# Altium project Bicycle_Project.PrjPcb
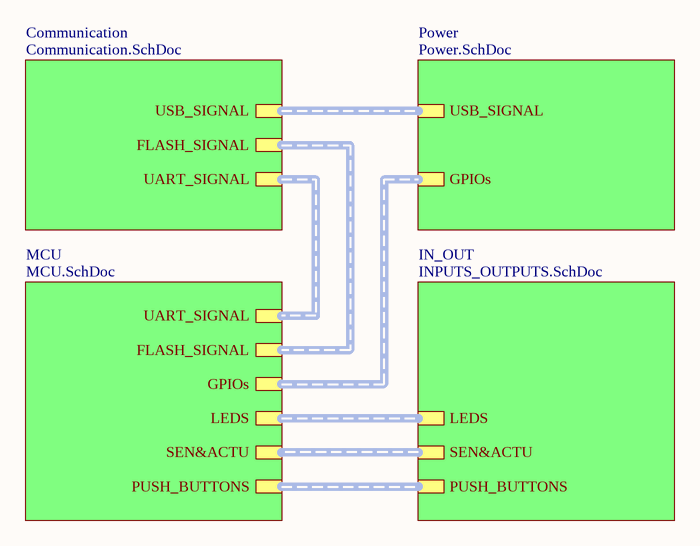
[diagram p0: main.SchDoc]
5 sheets, 108 parts. Net scope: hierarchical (ports join the sheet entries above them; power ports are global).
Board file: Bicycle_Project.PcbDoc
Sheets:
  main.SchDoc
    Communication = Communication.SchDoc
    MCU = MCU.SchDoc
    Power = Power.SchDoc
    IN_OUT = INPUTS_OUTPUTS.SchDoc

## Sheet main.SchDoc: BICYCLE_PROJECT
size A4; SheetNumber: 1; SheetTotal: 5

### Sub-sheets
Communication = Communication.SchDoc: USB_SIGNAL (harness USB_SIGNAL), UART_SIGNAL (harness UART_SIGNAL), FLASH_SIGNAL (harness FLASH_SIGNAL)
IN_OUT = INPUTS_OUTPUTS.SchDoc: LEDS (harness LEDS), PUSH_BUTTONS (harness PUSH_BUTTONS), SEN&ACTU (harness SENSORS&ACTUATORS)
MCU = MCU.SchDoc: UART_SIGNAL (harness UART_SIGNAL), LEDS (harness LEDS), PUSH_BUTTONS (harness PUSH_BUTTONS), FLASH_SIGNAL (harness FLASH_SIGNAL), SEN&ACTU (harness SENSORS&ACTUATORS), GPIOs (harness GPIOs)
Power = Power.SchDoc: USB_SIGNAL (harness USB_SIGNAL), GPIOs (harness GPIOs)

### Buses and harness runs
harness sheet Communication/FLASH_SIGNAL = sheet MCU/FLASH_SIGNAL
harness sheet Communication/UART_SIGNAL = sheet MCU/UART_SIGNAL
harness sheet Communication/USB_SIGNAL = sheet Power/USB_SIGNAL
harness sheet IN_OUT/LEDS = sheet MCU/LEDS
harness sheet IN_OUT/PUSH_BUTTONS = sheet MCU/PUSH_BUTTONS
harness sheet IN_OUT/SEN&ACTU = sheet MCU/SEN&ACTU
harness sheet MCU/GPIOs = sheet Power/GPIOs

## Sheet Communication.SchDoc
size A4; SheetNumber: 4; SheetTotal: 5
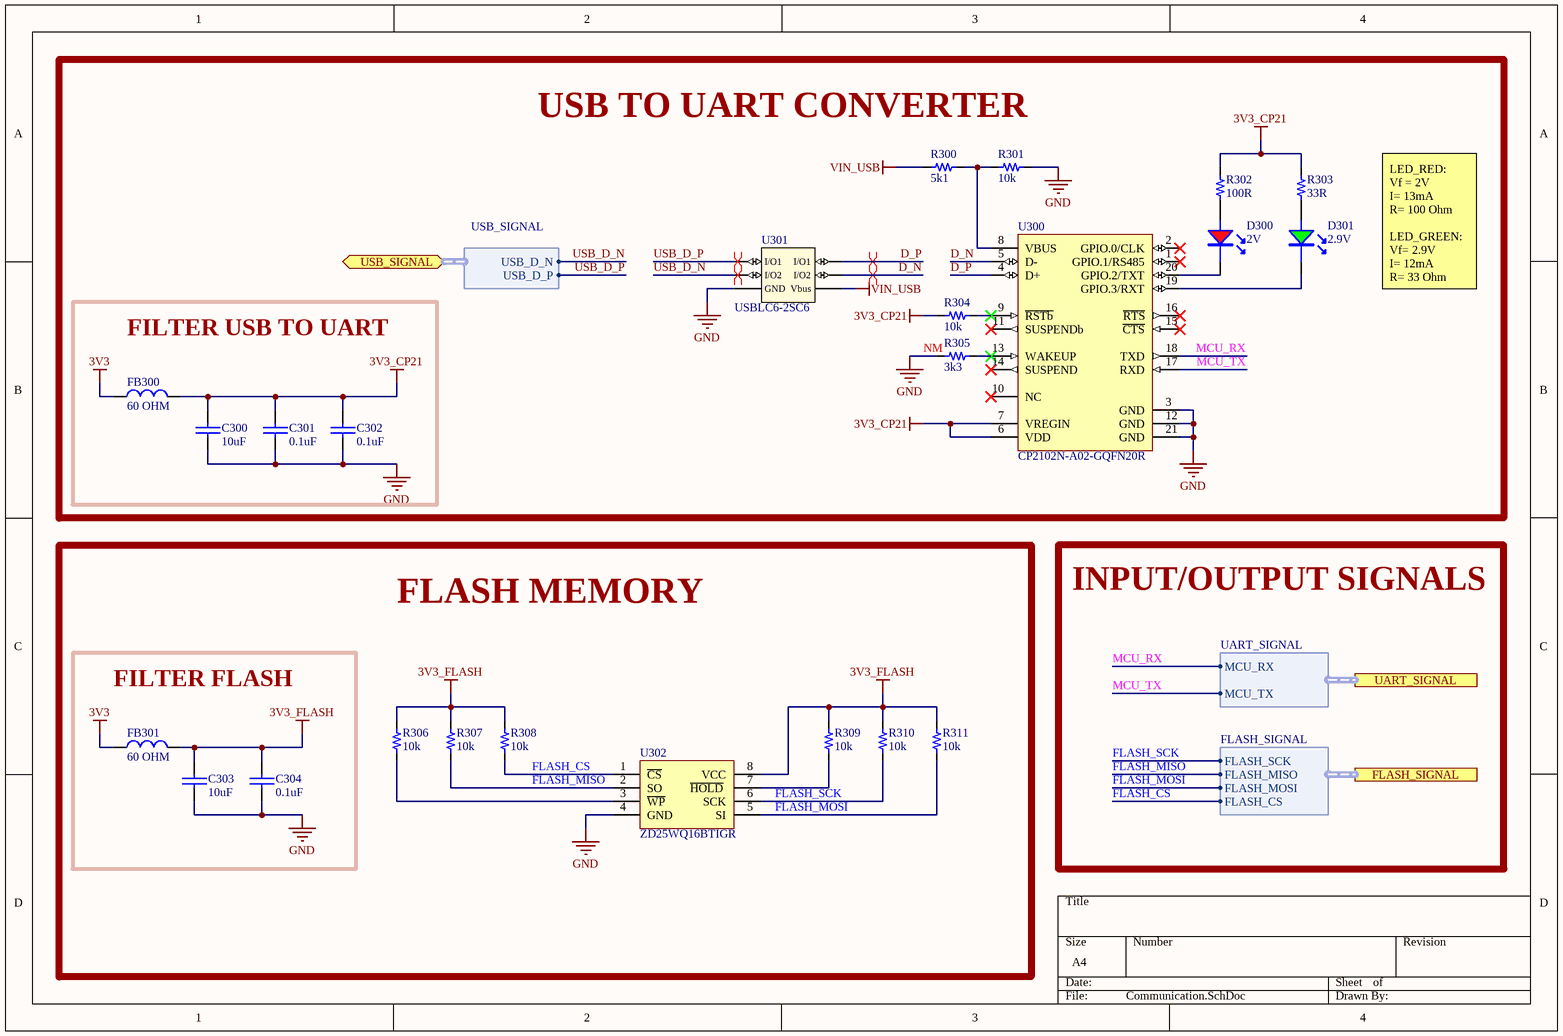
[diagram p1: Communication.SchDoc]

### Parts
C300  value 10uF  [0603_cap]  (hidden comment: 10uF 10V)
C301  value 0.1uF  [0603_cap]  (hidden comment: 0.1uF 50V)
C302  value 0.1uF  [0603_cap]  (hidden comment: 0.1uF 50V)
C303  value 10uF  [0603_cap]  (hidden comment: 10uF 10V)
C304  value 0.1uF  [0603_cap]  (hidden comment: 0.1uF 50V)
D300  2V  [0805_LED]
D301  2.9V  [0805_LED]
FB300  value 60 OHM  [0603_fb]  (hidden comment: 60OHM 2A)
FB301  value 60 OHM  [0603_fb]  (hidden comment: 60OHM 2A)
R300  value 5k1  [0603_res]  (hidden comment: 5k1 1/10W)
R301  value 10k  [0603_res]  (hidden comment: 10k 1/10W)
R302  value 100R  [0603_res]  (hidden comment: 100R 1/10W)
R303  value 33R  [0603_res]  (hidden comment: 33R 1/10W)
R304  value 10k  [0603_res]  (hidden comment: 10k 1/10W)
R305  value 3k3  Usage: NM  [0603_res]  (hidden comment: 3k3 1/10W)
R306  value 10k  [0603_res]  (hidden comment: 10k 1/10W)
R307  value 10k  [0603_res]  (hidden comment: 10k 1/10W)
R308  value 10k  [0603_res]  (hidden comment: 10k 1/10W)
R309  value 10k  [0603_res]  (hidden comment: 10k 1/10W)
R310  value 10k  [0603_res]  (hidden comment: 10k 1/10W)
R311  value 10k  [0603_res]  (hidden comment: 10k 1/10W)
U300  CP2102N-A02-GQFN20R  [WFQFN_20_EP_3X3MM]
U301  USBLC6-2SC6  [SOT_23_6]
U302  ZD25WQ16BTIGR  [SOIC_8_3.9mm]

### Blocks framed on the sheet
USB TO UART CONVERTER: D300 D301 R300-R305 U300 U301
FILTER USB TO UART: C300-C302 FB300
FLASH MEMORY: R306-R311 U302
FILTER FLASH: C303 C304 FB301

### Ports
FLASH_SIGNAL (harness FLASH_SIGNAL, see main[3B], MCU[4B]), UART_SIGNAL (harness UART_SIGNAL, see main[3B], MCU[4D]), USB_SIGNAL (bidir, harness USB_SIGNAL, see main[3B], Power[2A])

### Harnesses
USB_SIGNAL: USB_D_N, USB_D_P
UART_SIGNAL: MCU_TX, MCU_RX
FLASH_SIGNAL: FLASH_SCK, FLASH_MISO, FLASH_MOSI, FLASH_CS

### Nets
3V3: FB300.1 FB301.2
3V3_CP21: C300.1 C301.1 C302.1 FB300.2 R302.2 R303.2 R304.1 U300.6(VDD) U300.7(VREGIN)
3V3_FLASH: C303.1 C304.1 FB301.1 R306.2 R307.2 R308.1 R309.2 R310.2 R311.2 U302.8(VCC)
GND: C300.2 C301.2 C302.2 C303.2 C304.2 R301.2 R305.1 U300.3(GND) U300.12(GND) U300.21(GND) U301.2(GND) U302.4(GND)
VIN_USB: R300.1 U301.5(Vbus)
D_N: U300.5(D-) U301.4(I/O2)
D_P: U300.4(D+) U301.6(I/O1)
FLASH_CS: R308.2 U302.1(~{CS}) ; port FLASH_SIGNAL.FLASH_CS
FLASH_MISO: R307.1 U302.2(SO) ; port FLASH_SIGNAL.FLASH_MISO
FLASH_MOSI: R311.1 U302.5(SI) ; port FLASH_SIGNAL.FLASH_MOSI
FLASH_SCK: R310.1 U302.6(SCK) ; port FLASH_SIGNAL.FLASH_SCK
MCU_RX: U300.18(TXD) ; port UART_SIGNAL.MCU_RX
MCU_TX: U300.17(RXD) ; port UART_SIGNAL.MCU_TX
USB_D_N: U301.3(I/O2) ; port USB_SIGNAL.USB_D_N
USB_D_P: U301.1(I/O1) ; port USB_SIGNAL.USB_D_P
NetD300_1: D300.1(A) R302.1
NetD300_2: D300.2 U300.20(GPIO.2/TXT)
NetD301_1: D301.1(A) R303.1
NetD301_2: D301.2 U300.19(GPIO.3/RXT)
NetR300_2: R300.2 R301.1 U300.8(VBUS)
NetR304_2: R304.2 U300.9(~{RSTb})
NetR305_2: R305.2 U300.13(WAKEUP)
NetR306_1: R306.1 U302.3(~{WP})
NetR309_1: R309.1 U302.7(~{HOLD})

Not connected (* = marked no-connect by the designer): U300 1(GPIO.1/RS485)* 2(GPIO.0/CLK)* 10(NC)* 11(SUSPENDb)* 14(SUSPEND)* 15(~{CTS})* 16(~{RTS})*

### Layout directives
differential pair: D_N, D_P, USB_D_N, USB_D_P

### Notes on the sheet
- LED_RED:
  Vf = 2V
  I= 13mA
  R= 100 Ohm
  LED_GREEN:
  Vf= 2.9V
  I= 12mA
  R= 33 Ohm
- INPUT/OUTPUT SIGNALS

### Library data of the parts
C300 C303 = Cap_10uF_0603_10V: 10V 10uF X5R ±10% 0603 Multilayer Ceramic Capacitors MLCC - SMD/SMT ROHS; Manufacturer: CCTC; Manufacturer Part Number: TCC0603X5R106K100CT
C301 C302 C304 = Cap_0.1uF_0603_50V: 50V 100nF Y5V -20%~+80% 0603 Multilayer Ceramic Capacitors MLCC - SMD/SMT ROHS; Manufacturer: Walsin Tech Corp; Manufacturer Part Number: 0603F104Z500CT
D300 = LED_0805_RED: LED RED CLEAR 0805 SMD; Manufacturer: XINGLIGHT; Manufacturer Part Number: XL-2012SURC
D301 = LED_0805_Green: LED GREEN CLEAR 0805 SMD; Manufacturer: XINGLIGHT; Manufacturer Part Number: XL-2012UGC
FB300 FB301 = FB_60_0603_2A: 2A 1 100mΩ 60Ω@100MHz ±25% 0603 Ferrite Beads ROHS; Manufacturer: TAI-TECH; Manufacturer Part Number: HCB1608KF-600T20
R300 = Res_5k1_0603_1/10W: RES SMD 5k1 OHM 5% 1/10W 0603; Manufacturer: FOJAN; Manufacturer Part Number: FRC0603J512 TS
R301 R304 R306-R311 = Res_10k_0603_1/10W: RES SMD 10k OHM 5% 1/10W 0603; Manufacturer: FOJAN; Manufacturer Part Number: FRC0603J103TS
R302 = Res_100R_0603_1/10W: RES SMD 100R OHM 5% 1/10W 0603; Manufacturer: FOJAN; Manufacturer Part Number: FRC0603J101 TS
R303 = Res_33R_0603_1/10W: RES SMD 33R OHM 5% 1/10W 0603; Manufacturer: FOJAN; Manufacturer Part Number: FRC0603J330 TS
R305 = Res_3k3_0603_1/10W: RES SMD 3k3 OHM 5% 1/10W 0603; Manufacturer: FOJAN; Manufacturer Part Number: FRC0603J332 TS
U300 = IC_SGL_USB2UART-BRIDGE_20QFN: IC USB TO UART BRIDGE QFN20; Manufacturer: Silicon Labs
U301 = TVS_5.25V_2CH_SOT_23_6: TVS DIODE 5.25V 17V SOT23-6; Manufacturer: STMicroelectronics
U302 = IC_FLASH_ZD25WQ16BTIGR_8SOP: IC FLASH 16M SPI 85MHZ 8SOP; Manufacturer: Zetta

## Sheet MCU.SchDoc
size A4; SheetNumber: 2; SheetTotal: 5
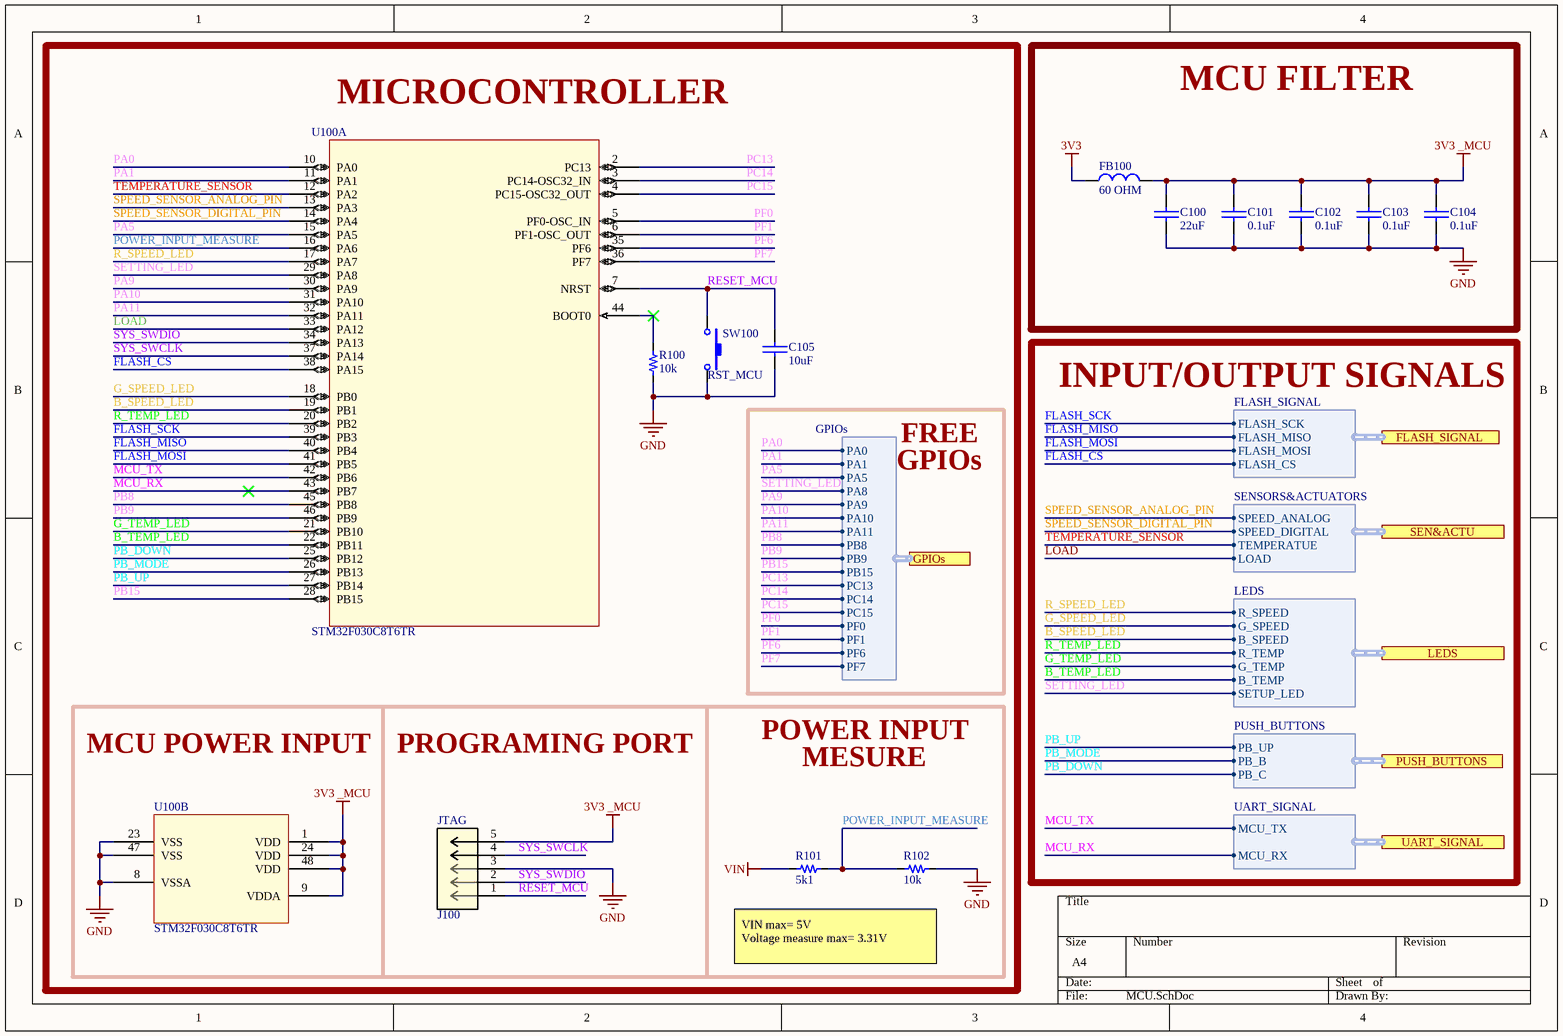
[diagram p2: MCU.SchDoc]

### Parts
C100  value 22uF  [0603_cap]  (hidden comment: 22uF 6V3)
C101  value 0.1uF  [0603_cap]  (hidden comment: 0.1uF 50V)
C102  value 0.1uF  [0603_cap]  (hidden comment: 0.1uF 50V)
C103  value 0.1uF  [0603_cap]  (hidden comment: 0.1uF 50V)
C104  value 0.1uF  [0603_cap]  (hidden comment: 0.1uF 50V)
C105  value 10uF  [0603_cap]  (hidden comment: 10uF 10V)
FB100  value 60 OHM  [0603_fb]  (hidden comment: 60OHM 2A)
J100  JTAG  [CON_5X1_TH_2.54MM]
R100  value 10k  [0603_res]  (hidden comment: 10k 1/10W)
R101  value 5k1  [0603_res]  (hidden comment: 5k1 1/10W)
R102  value 10k  [0603_res]  (hidden comment: 10k 1/10W)
SW100  RST_MCU  [Sw_PUSH_4.5x4.5x5mm]
U100  STM32F030C8T6TR  [LQFP48_7x7mm]  (parts A,B of 2)

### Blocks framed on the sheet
MICROCONTROLLER: C105 J100 R100-R102 SW100 U100
MCU FILTER: C100-C104 FB100

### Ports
FLASH_SIGNAL (harness FLASH_SIGNAL, see main[2B], Communication[4D]), GPIOs (harness GPIOs, see main[2C], Power[3C]), LEDS (harness LEDS, see main[2C], INPUTS_OUTPUTS[4B]), PUSH_BUTTONS (harness PUSH_BUTTONS, see main[2C], INPUTS_OUTPUTS[4B]), SEN&ACTU (harness SENSORS&ACTUATORS, see main[2C], INPUTS_OUTPUTS[4A]), UART_SIGNAL (harness UART_SIGNAL, see main[2B], Communication[4C])

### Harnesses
LEDS: R_SPEED, G_SPEED, B_SPEED, R_TEMP, G_TEMP, B_TEMP, SETUP_LED
SENSORS&ACTUATORS: SPEED_ANALOG, SPEED_DIGITAL, TEMPERATUE, LOAD
PUSH_BUTTONS: PB_UP, PB_B, PB_C
FLASH_SIGNAL: FLASH_SCK, FLASH_MISO, FLASH_MOSI, FLASH_CS
UART_SIGNAL: MCU_TX, MCU_RX
GPIOs: PA0, PA1, PA5, PA8, PA9, PA10, PA11, PB8, PB9, PB15, PC13, PC14, PC15, PF0, PF1, PF6, PF7

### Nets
3V3: FB100.2
3V3 _MCU: C100.1 C101.1 C102.1 C103.1 C104.1 FB100.1 J100.5 U100.1(VDD) U100.9(VDDA) U100.24(VDD) U100.48(VDD)
GND: C100.2 C101.2 C102.2 C103.2 C104.2 C105.2 J100.3 R100.2 R102.1 SW100.2 U100.8(VSSA) U100.23(VSS) U100.47(VSS)
VIN: R101.2
B_SPEED_LED: U100.19(PB1) ; port LEDS.B_SPEED
B_TEMP_LED: U100.22(PB11) ; port LEDS.B_TEMP
FLASH_CS: U100.38(PA15) ; port FLASH_SIGNAL.FLASH_CS
FLASH_MISO: U100.40(PB4) ; port FLASH_SIGNAL.FLASH_MISO
FLASH_MOSI: U100.41(PB5) ; port FLASH_SIGNAL.FLASH_MOSI
FLASH_SCK: U100.39(PB3) ; port FLASH_SIGNAL.FLASH_SCK
G_SPEED_LED: U100.18(PB0) ; port LEDS.G_SPEED
G_TEMP_LED: U100.21(PB10) ; port LEDS.G_TEMP
LOAD: U100.33(PA12) ; port SEN&ACTU.LOAD
MCU_RX: U100.43(PB7) ; port UART_SIGNAL.MCU_RX
MCU_TX: U100.42(PB6) ; port UART_SIGNAL.MCU_TX
PA0: U100.10(PA0) ; port GPIOs.PA0
PA1: U100.11(PA1) ; port GPIOs.PA1
PA5: U100.15(PA5) ; port GPIOs.PA5
PA9: U100.30(PA9) ; port GPIOs.PA9
PA10: U100.31(PA10) ; port GPIOs.PA10
PA11: U100.32(PA11) ; port GPIOs.PA11
PB8: U100.45(PB8) ; port GPIOs.PB8
PB9: U100.46(PB9) ; port GPIOs.PB9
PB15: U100.28(PB15) ; port GPIOs.PB15
PB_DOWN: U100.25(PB12) ; port PUSH_BUTTONS.PB_C
PB_MODE: U100.26(PB13) ; port PUSH_BUTTONS.PB_B
PB_UP: U100.27(PB14) ; port PUSH_BUTTONS.PB_UP
PC13: U100.2(PC13) ; port GPIOs.PC13
PC14: U100.3(PC14-OSC32_IN) ; port GPIOs.PC14
PC15: U100.4(PC15-OSC32_OUT) ; port GPIOs.PC15
PF0: U100.5(PF0-OSC_IN) ; port GPIOs.PF0
PF1: U100.6(PF1-OSC_OUT) ; port GPIOs.PF1
PF6: U100.35(PF6) ; port GPIOs.PF6
PF7: U100.36(PF7) ; port GPIOs.PF7
POWER_INPUT_MEASURE: R101.1 R102.2 U100.16(PA6)
R_SPEED_LED: U100.17(PA7) ; port LEDS.R_SPEED
R_TEMP_LED: U100.20(PB2) ; port LEDS.R_TEMP
RESET_MCU: C105.1 J100.1 SW100.1 U100.7(NRST)
SETTING_LED: U100.29(PA8) ; port LEDS.SETUP_LED, port GPIOs.PA8
SPEED_SENSOR_ANALOG_PIN: U100.13(PA3) ; port SEN&ACTU.SPEED_ANALOG
SPEED_SENSOR_DIGITAL_PIN: U100.14(PA4) ; port SEN&ACTU.SPEED_DIGITAL
SYS_SWCLK: J100.4 U100.37(PA14)
SYS_SWDIO: J100.2 U100.34(PA13)
TEMPERATURE_SENSOR: U100.12(PA2) ; port SEN&ACTU.TEMPERATUE
NetR100_1: R100.1 U100.44(BOOT0)

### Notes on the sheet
- FREE
- INPUT/OUTPUT SIGNALS
- GPIOs
- MCU POWER INPUT
- PROGRAMING PORT
- POWER INPUT
- MESURE
- VIN max= 5V
  Voltage measure max= 3.31V

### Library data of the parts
C100 = Cap_22uF_0805_6V3: 6.3V 22uF X5R ±20% 0805 Multilayer Ceramic Capacitors MLCC - SMD/SMT ROHS; Manufacturer: Samsung Electro-Mechanics; Manufacturer Part Number: CL21A226MQQNNNE
C101-C104 = Cap_0.1uF_0603_50V: as C301 on sheet Communication
C105 = Cap_10uF_0603_10V: as C300 on sheet Communication
FB100 = FB_60_0603_2A: as FB300 on sheet Communication
J100 = Con_5X1_TH_2.54mm: CONN HEADER VERT 5POS 2.54MM; Manufacturer: Amphenol ICC (FCI); Manufacturer Part Number: 10129378-905001BLF
R100 R102 = Res_10k_0603_1/10W: as R301 on sheet Communication
R101 = Res_5k1_0603_1/10W: as R300 on sheet Communication
SW100 = Sw_PUSH_4.5x4.5x5.0xmm: SWITCH TACTILE SPST-NO 0.05A 12V; Manufacturer: BZCN; Manufacturer Part Number: TSC015A05026A
U100 = IC_STM32F030C8T6TR_LQFP48_7x7MM: IC MCU 32BIT 64KB FLASH 48LQFP; Manufacturer: STMicroelectronics

## Sheet Power.SchDoc
size A4; SheetNumber: 3; SheetTotal: 5
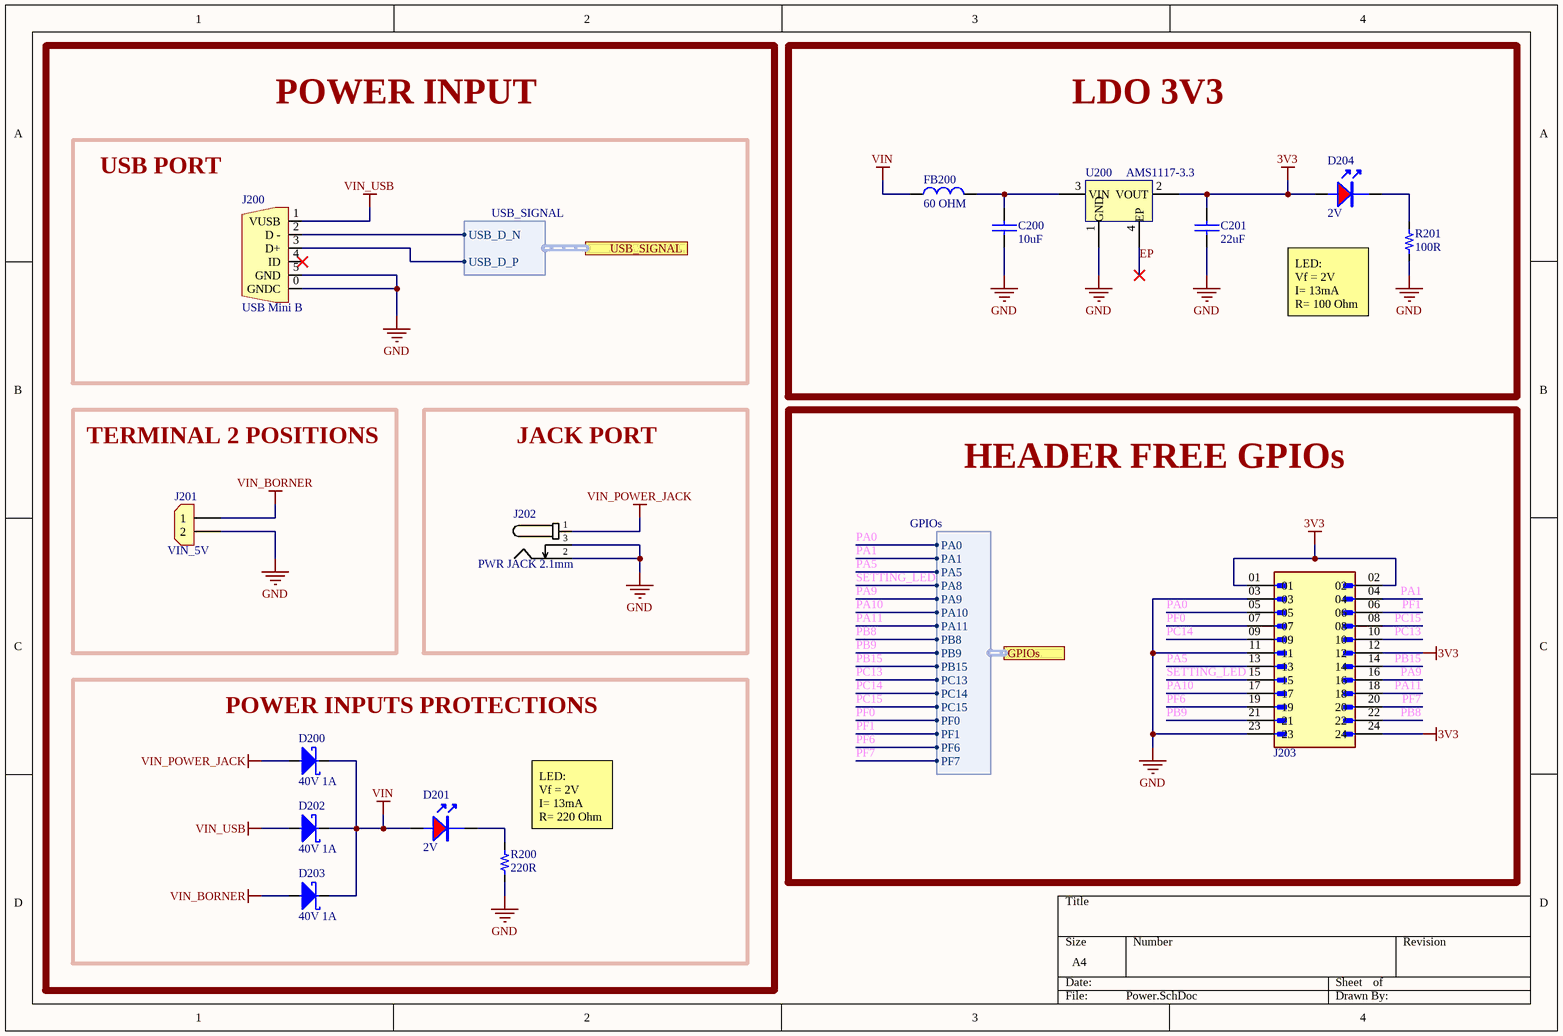
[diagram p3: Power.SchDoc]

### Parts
C200  value 10uF  [0603_cap]  (hidden comment: 10uF 10V)
C201  value 22uF  [0603_cap]  (hidden comment: 22uF 6V3)
D200  40V 1A  [SOD_123]
D201  2V  [0805_LED]
D202  40V 1A  [SOD_123]
D203  40V 1A  [SOD_123]
D204  2V  [0805_LED]
FB200  value 60 OHM  [0603_fb]  (hidden comment: 60OHM 2A)
J200  USB Mini B  [CON_5x1_SMD_miniUSB_B]
J201  VIN_5V  [CON_2x1_TH_5MM]
J202  PWR JACK 2.1mm  [CON_POWER_BARREL_2.1MM_3CONN]
J203  10129381-924001BLF  [CON_2x12_th_2.54MM]  (value not drawn)
R200  value 220R  [0603_res]  (hidden comment: 220R 1/10W)
R201  value 100R  [0603_res]  (hidden comment: 100R 1/10W)
U200  AMS1117-3.3  [SOT_223]

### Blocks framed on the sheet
LDO 3V3: C200 C201 D204 FB200 R201 U200
USB PORT: J200
TERMINAL 2 POSITIONS: J201
JACK PORT: J202
HEADER FREE GPIOs: J203
POWER INPUTS PROTECTIONS: D200-D203 R200

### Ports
GPIOs (harness GPIOs, see main[3B], MCU[3C]), USB_SIGNAL (harness USB_SIGNAL, see main[3B], Communication[1B])

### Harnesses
USB_SIGNAL: USB_D_N, USB_D_P
GPIOs: PA0, PA1, PA5, PA8, PA9, PA10, PA11, PB8, PB9, PB15, PC13, PC14, PC15, PF0, PF1, PF6, PF7

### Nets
3V3: C201.1 D204.1(A) J203.01 J203.02 J203.12 J203.24 U200.2(VOUT)
GND: C200.2 C201.2 J200.0(GNDC) J200.5(GND) J201.2 J202.2 J202.3 J203.03 J203.11 J203.23 R200.1 R201.1 U200.1(GND)
VIN: D200.1 D201.1(A) D202.1 D203.1 FB200.1
VIN_BORNER: D203.2 J201.1
VIN_POWER_JACK: D200.2 J202.1
VIN_USB: D202.2 J200.1(VUSB)
EP: U200.4(EP)
PA0: J203.05 ; port GPIOs.PA0
PA1: J203.04 ; port GPIOs.PA1
PA5: J203.13 ; port GPIOs.PA5
PA9: J203.16 ; port GPIOs.PA9
PA10: J203.17 ; port GPIOs.PA10
PA11: J203.18 ; port GPIOs.PA11
PB8: J203.22 ; port GPIOs.PB8
PB9: J203.21 ; port GPIOs.PB9
PB15: J203.14 ; port GPIOs.PB15
PC13: J203.10 ; port GPIOs.PC13
PC14: J203.09 ; port GPIOs.PC14
PC15: J203.08 ; port GPIOs.PC15
PF0: J203.07 ; port GPIOs.PF0
PF1: J203.06 ; port GPIOs.PF1
PF6: J203.19 ; port GPIOs.PF6
PF7: J203.20 ; port GPIOs.PF7
SETTING_LED: J203.15 ; port GPIOs.PA8
USB_D_N: J200.2(D_-) ; port USB_SIGNAL.USB_D_N
USB_D_P: J200.3(D+) ; port USB_SIGNAL.USB_D_P
NetC200_1: C200.1 FB200.2 U200.3(VIN)
NetD201_2: D201.2 R200.2
NetD204_2: D204.2 R201.2

Not connected (* = marked no-connect by the designer): J200 4(ID)*

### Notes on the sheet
- POWER INPUT
- LED:
  Vf = 2V
  I= 13mA
  R= 100 Ohm
- (near R200) LED:
  Vf = 2V
  I= 13mA
  R= 220 Ohm

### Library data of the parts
C200 = Cap_10uF_0603_10V: as C300 on sheet Communication
C201 = Cap_22uF_0805_6V3: as C100 on sheet MCU
D200 D202 D203 = D_Schottky_40V_1A_SOD_123F: DIODE SCHOTTKY 40V 1A SOD123F; Manufacturer: Shanghai Prisemi Elec; Manufacturer Part Number: PSBD1DF40V1H
D201 D204 = LED_0805_RED: as D300 on sheet Communication
FB200 = FB_60_0603_2A: as FB300 on sheet Communication
J200 = Con_Mini_USB_B: CONN RCPT USB2.0 MINI B SMD R/A; Manufacturer Part Number: KH-MINI-SMT-5P-Cu; Manufacturer: EDAC Inc.
J201 = Con_2x1_TH_5mm: 2POS 5MM; Manufacturer: JILN; Manufacturer Part Number: JL126-50002G01
J202 = Con_Power_Jack_2.1mm_3pins: CONN PWR JACK 2X5.5MM SOLDER; Manufacturer: HCTL; Manufacturer Part Number: HC-DC-005-2.0T
J203 = Con_2x12_TH_2.54mm: CONN HEADER VERT 24POS 2.54MM; Manufacturer: Amphenol ICC (FCI)
R200 = Res_220R_0603_1/10W: RES SMD 220R OHM 5% 1/10W 0603; Manufacturer: FOJAN; Manufacturer Part Number: FRC0603J221 TS
R201 = Res_100R_0603_1/10W: as R302 on sheet Communication
U200 = LDO_3V3_1A_FIXED: 1A 60dB@(120Hz) Fixed 3.3V Positive 18V SOT-223 Linear Voltage Regulators (LDO) ROHS; Manufacturer: UMW(Youtai Semiconductor Co., Ltd.)

## Sheet INPUTS_OUTPUTS.SchDoc
size A; SheetNumber: 5; SheetTotal: 5
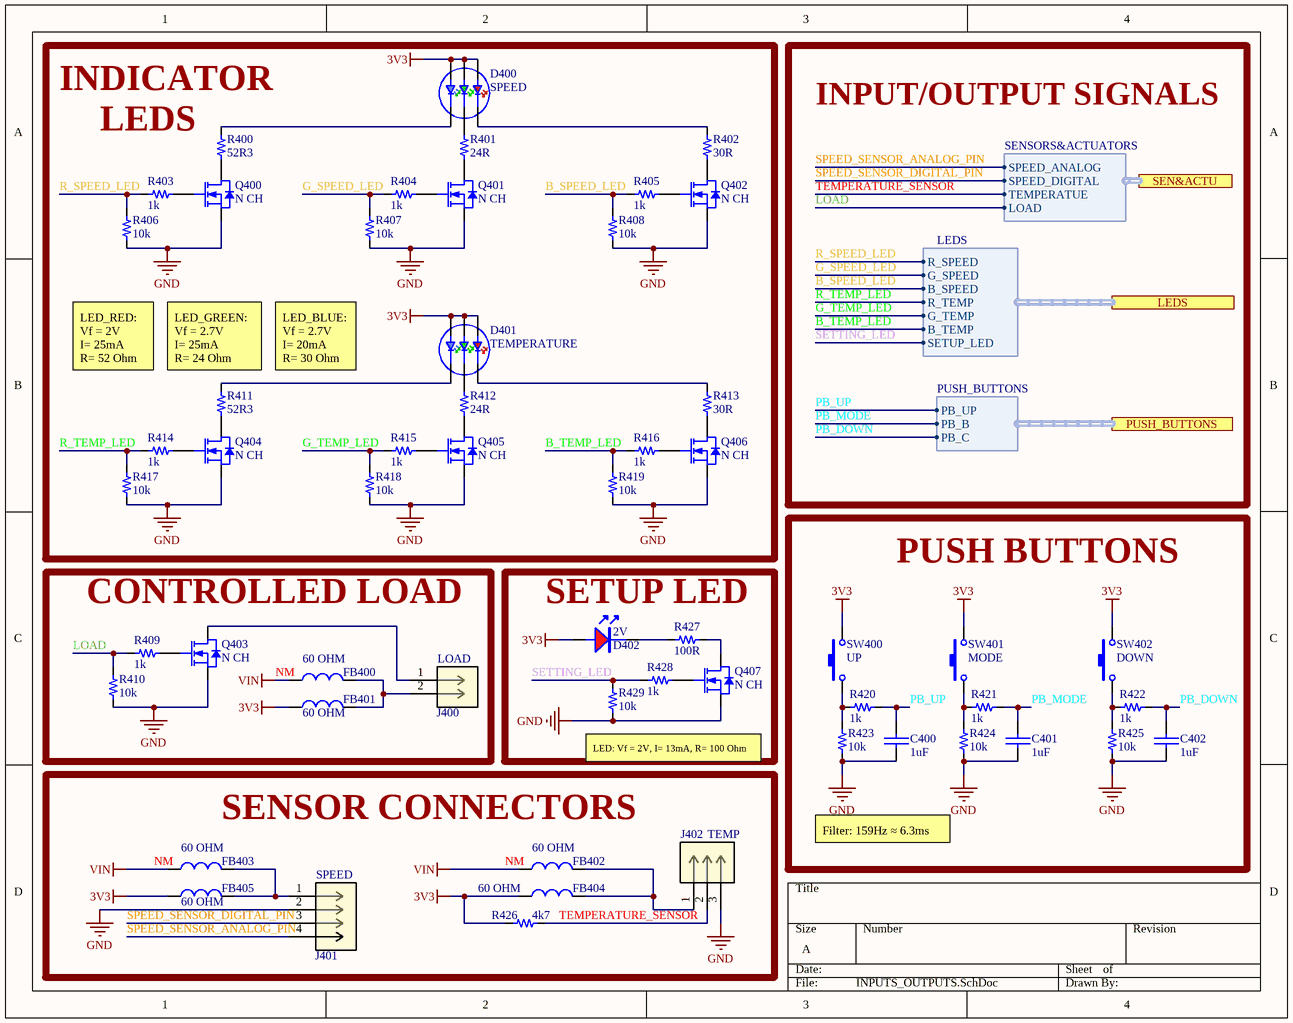
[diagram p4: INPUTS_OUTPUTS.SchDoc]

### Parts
C400  value 1uF  [0603_cap]  (hidden comment: 1uF 50V)
C401  value 1uF  [0603_cap]  (hidden comment: 1uF 50V)
C402  value 1uF  [0603_cap]  (hidden comment: 1uF 50V)
D400  SPEED  [RGB_NS_3.5X3.7]
D401  TEMPERATURE  [RGB_NS_3.5X3.7]
D402  2V  [0805_LED]
FB400  value 60 OHM  Usage: NM  [0603_fb]  (hidden comment: 60OHM 2A)
FB401  value 60 OHM  [0603_fb]  (hidden comment: 60OHM 2A)
FB402  value 60 OHM  Usage: NM  [0603_fb]  (hidden comment: 60OHM 2A)
FB403  value 60 OHM  Usage: NM  [0603_fb]  (hidden comment: 60OHM 2A)
FB404  value 60 OHM  [0603_fb]  (hidden comment: 60OHM 2A)
FB405  value 60 OHM  [0603_fb]  (hidden comment: 60OHM 2A)
J400  LOAD  [CON_2X1_TH_2.54MM]
J401  SPEED  [CON_4X1_TH_2.54MM]
J402  TEMP  [CON_3X1_TH_2.54MM]
Q400  N CH  [SOT_23_3]
Q401  N CH  [SOT_23_3]
Q402  N CH  [SOT_23_3]
Q403  N CH  [SOT_23_3]
Q404  N CH  [SOT_23_3]
Q405  N CH  [SOT_23_3]
Q406  N CH  [SOT_23_3]
Q407  N CH  [SOT_23_3]
R400  value 52R3  [0603_res]  (hidden comment: 52R3 1/10W)
R401  value 24R  [0603_res]  (hidden comment: 24R 1/10W)
R402  value 30R  [0603_res]  (hidden comment: 30 1/10W)
R403  value 1k  [0603_res]  (hidden comment: 1k 1/10W)
R404  value 1k  [0603_res]  (hidden comment: 1k 1/10W)
R405  value 1k  [0603_res]  (hidden comment: 1k 1/10W)
R406  value 10k  [0603_res]  (hidden comment: 10k 1/10W)
R407  value 10k  [0603_res]  (hidden comment: 10k 1/10W)
R408  value 10k  [0603_res]  (hidden comment: 10k 1/10W)
R409  value 1k  [0603_res]  (hidden comment: 1k 1/10W)
R410  value 10k  [0603_res]  (hidden comment: 10k 1/10W)
R411  value 52R3  [0603_res]  (hidden comment: 52R3 1/10W)
R412  value 24R  [0603_res]  (hidden comment: 24R 1/10W)
R413  value 30R  [0603_res]  (hidden comment: 30 1/10W)
R414  value 1k  [0603_res]  (hidden comment: 1k 1/10W)
R415  value 1k  [0603_res]  (hidden comment: 1k 1/10W)
R416  value 1k  [0603_res]  (hidden comment: 1k 1/10W)
R417  value 10k  [0603_res]  (hidden comment: 10k 1/10W)
R418  value 10k  [0603_res]  (hidden comment: 10k 1/10W)
R419  value 10k  [0603_res]  (hidden comment: 10k 1/10W)
R420  value 1k  [0603_res]  (hidden comment: 1k 1/10W)
R421  value 1k  [0603_res]  (hidden comment: 1k 1/10W)
R422  value 1k  [0603_res]  (hidden comment: 1k 1/10W)
R423  value 10k  [0603_res]  (hidden comment: 10k 1/10W)
R424  value 10k  [0603_res]  (hidden comment: 10k 1/10W)
R425  value 10k  [0603_res]  (hidden comment: 10k 1/10W)
R426  value 4k7  [0603_res]  (hidden comment: 4k7 1/10W)
R427  value 100R  [0603_res]  (hidden comment: 100R 1/10W)
R428  value 1k  [0603_res]  (hidden comment: 1k 1/10W)
R429  value 10k  [0603_res]  (hidden comment: 10k 1/10W)
SW400  UP  [Sw_PUSH_4.5x4.5x5mm]
SW401  MODE  [Sw_PUSH_4.5x4.5x5mm]
SW402  DOWN  [Sw_PUSH_4.5x4.5x5mm]

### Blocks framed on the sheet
PUSH BUTTONS: C400-C402 R420-R425 SW400-SW402
CONTROLLED LOAD: FB400 FB401 J400 Q403 R409 R410
SETUP LED: D402 Q407 R427-R429
SENSOR CONNECTORS: FB402-FB405 J401 J402 R426

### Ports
LEDS (harness LEDS, see main[3C], MCU[4C]), PUSH_BUTTONS (harness PUSH_BUTTONS, see main[3C], MCU[4C]), SEN&ACTU (harness SENSORS&ACTUATORS, see main[3C], MCU[4C])

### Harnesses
LEDS: R_SPEED, G_SPEED, B_SPEED, R_TEMP, G_TEMP, B_TEMP, SETUP_LED
SENSORS&ACTUATORS: SPEED_ANALOG, SPEED_DIGITAL, TEMPERATUE, LOAD
PUSH_BUTTONS: PB_UP, PB_B, PB_C

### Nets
3V3: D400.4 D400.5 D400.6 D401.4 D401.5 D401.6 D402.1(A) FB401.1 FB404.1 FB405.1 R426.1 SW400.2 SW401.2 SW402.2
GND: C400.1 C401.1 C402.1 J401.2 J402.3 Q400.2(S) Q401.2(S) Q402.2(S) Q403.2(S) Q404.2(S) Q405.2(S) Q406.2(S) Q407.2(S) R406.1 R407.1 R408.1 R410.1 R417.1 R418.1 R419.1 R423.1 R424.1 R425.1 R429.1
VIN: FB400.1 FB402.1 FB403.1
B_SPEED_LED: R405.1 R408.2 ; port LEDS.B_SPEED
B_TEMP_LED: R416.1 R419.2 ; port LEDS.B_TEMP
G_SPEED_LED: R404.1 R407.2 ; port LEDS.G_SPEED
G_TEMP_LED: R415.1 R418.2 ; port LEDS.G_TEMP
LOAD: R409.1 R410.2 ; port SEN&ACTU.LOAD
PB_DOWN: C402.2 R422.2 ; port PUSH_BUTTONS.PB_C
PB_MODE: C401.2 R421.2 ; port PUSH_BUTTONS.PB_B
PB_UP: C400.2 R420.2 ; port PUSH_BUTTONS.PB_UP
R_SPEED_LED: R403.1 R406.2 ; port LEDS.R_SPEED
R_TEMP_LED: R414.1 R417.2 ; port LEDS.R_TEMP
SETTING_LED: R428.1 R429.2 ; port LEDS.SETUP_LED
SPEED_SENSOR_ANALOG_PIN: J401.4 ; port SEN&ACTU.SPEED_ANALOG
SPEED_SENSOR_DIGITAL_PIN: J401.3 ; port SEN&ACTU.SPEED_DIGITAL
TEMPERATURE_SENSOR: J402.2 R426.2 ; port SEN&ACTU.TEMPERATUE
NetD400_1: D400.1 R400.2
NetD400_2: D400.2 R401.2
NetD400_3: D400.3 R402.2
NetD401_1: D401.1 R411.2
NetD401_2: D401.2 R412.2
NetD401_3: D401.3 R413.2
NetD402_2: D402.2 R427.2
NetFB400_2: FB400.2 FB401.2 J400.2
NetFB402_2: FB402.2 FB404.2 J402.1
NetFB403_2: FB403.2 FB405.2 J401.1
NetJ400_1: J400.1 Q403.3(D)
NetQ400_1: Q400.1(G) R403.2
NetQ400_3: Q400.3(D) R400.1
NetQ401_1: Q401.1(G) R404.2
NetQ401_3: Q401.3(D) R401.1
NetQ402_1: Q402.1(G) R405.2
NetQ402_3: Q402.3(D) R402.1
NetQ403_1: Q403.1(G) R409.2
NetQ404_1: Q404.1(G) R414.2
NetQ404_3: Q404.3(D) R411.1
NetQ405_1: Q405.1(G) R415.2
NetQ405_3: Q405.3(D) R412.1
NetQ406_1: Q406.1(G) R416.2
NetQ406_3: Q406.3(D) R413.1
NetQ407_1: Q407.1(G) R428.2
NetQ407_3: Q407.3(D) R427.1
NetR420_1: R420.1 R423.2 SW400.1
NetR421_1: R421.1 R424.2 SW401.1
NetR422_1: R422.1 R425.2 SW402.1

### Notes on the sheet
- (near R400) INDICATOR
- LEDS
- INPUT/OUTPUT SIGNALS
- LED_RED:
  Vf = 2V
  I= 25mA
  R= 52 Ohm
- (near R411) LED_GREEN:
  Vf = 2.7V
  I= 25mA
  R= 24 Ohm
- LED_BLUE:
  Vf = 2.7V
  I= 20mA
  R= 30 Ohm
- LED: Vf = 2V, I= 13mA, R= 100 Ohm
- Filter: 159Hz ≈ 6.3ms

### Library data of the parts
C400-C402 = Cap_1uF_0603_50V: 50V 1uF X5R ±10% 0603 Multilayer Ceramic Capacitors MLCC - SMD/SMT ROHS; Manufacturer: Samsung Electro-Mechanics; Manufacturer Part Number: CL10A105KB8NNNC
D400 D401 = LED_RGB_3535_SMD: -30℃~+85℃ RGB 110° 3535(mm) Light Emitting Diodes (LED) ROHS; Manufacturer: Foshan NationStar Optoelectronics; Manufacturer Part Number: RS-3535MWAM
D402 = LED_0805_RED: as D300 on sheet Communication
FB400-FB405 = FB_60_0603_2A: as FB300 on sheet Communication
J400 = Con_2x1_TH_2.54mm: CONN HEADER VERT 2POS 2.54MM; Manufacturer: Amphenol ICC (FCI); Manufacturer Part Number: 10129378-902001BLF
J401 = Con_4X1_TH_2.54mm: CONN HEADER VERT 4POS 2.54MM; Manufacturer: Amphenol ICC (FCI); Manufacturer Part Number: 10129378-904001BLF
J402 = Con_3X1_TH_2.54mm: CONN HEADER VERT 3POS 2.54MM; Manufacturer: Amphenol ICC (FCI); Manufacturer Part Number: 10129378-903001BLF
Q400-Q407 = Q_NFET_20V_3.2A_SOT23: MOSFET N-CH 20V SOT23; Manufacturer: Doeshare; Manufacturer Part Number: DN2302S
R400 R411 = Res_52R3_0603_1/10W_1: RES SMD 52R3 OHM 1% 1/10W 0603; Manufacturer: FOJAN; Manufacturer Part Number: FRC0603F52R3TS
R401 R412 = Res_24R_0603_1/10W: RES SMD 24R OHM 5% 1/10W 0603; Manufacturer: FOJAN; Manufacturer Part Number: FRC0603J240 TS
R402 R413 = Res_30R_0603_1/10W: RES SMD 30R OHM 1% 1/10W 0603; Manufacturer: FOJAN; Manufacturer Part Number: FRC0603F30R0TS
R403-R405 R409 R414-R416 R420-R422 R428 = Res_1k_0603_1/10W: RES SMD 1k OHM 5% 1/10W 0603; Manufacturer: FOJAN; Manufacturer Part Number: FRC0603J102 TS
R406-R408 R410 R417-R419 R423-R425 R429 = Res_10k_0603_1/10W: as R301 on sheet Communication
R426 = Res_4k7_0603_1/10W: RES SMD 4k7 OHM 5% 1/10W 0603; Manufacturer: FOJAN; Manufacturer Part Number: FRC0603J472 TS
R427 = Res_100R_0603_1/10W: as R302 on sheet Communication
SW400-SW402 = Sw_PUSH_4.5x4.5x5.0xmm: as SW100 on sheet MCU

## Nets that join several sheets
3V3: Communication (FB300.1 FB301.2), MCU (FB100.2), Power (7 pins), INPUTS_OUTPUTS (14 pins)
GND: Communication (12 pins), MCU (13 pins), Power (13 pins), INPUTS_OUTPUTS (24 pins)
VIN: MCU (R101.2), Power (5 pins), INPUTS_OUTPUTS (FB400.1 FB402.1 FB403.1)
VIN_USB: Communication (R300.1 U301.5), Power (D202.2 J200.1)
B_SPEED_LED: MCU (U100.19), INPUTS_OUTPUTS (R405.1 R408.2)
B_TEMP_LED: MCU (U100.22), INPUTS_OUTPUTS (R416.1 R419.2)
FLASH_CS: Communication (R308.2 U302.1), MCU (U100.38)
FLASH_MISO: Communication (R307.1 U302.2), MCU (U100.40)
FLASH_MOSI: Communication (R311.1 U302.5), MCU (U100.41)
FLASH_SCK: Communication (R310.1 U302.6), MCU (U100.39)
G_SPEED_LED: MCU (U100.18), INPUTS_OUTPUTS (R404.1 R407.2)
G_TEMP_LED: MCU (U100.21), INPUTS_OUTPUTS (R415.1 R418.2)
LOAD: MCU (U100.33), INPUTS_OUTPUTS (R409.1 R410.2)
MCU_RX: Communication (U300.18), MCU (U100.43)
MCU_TX: Communication (U300.17), MCU (U100.42)
PA0: MCU (U100.10), Power (J203.05)
PA1: MCU (U100.11), Power (J203.04)
PA5: MCU (U100.15), Power (J203.13)
PA9: MCU (U100.30), Power (J203.16)
PA10: MCU (U100.31), Power (J203.17)
PA11: MCU (U100.32), Power (J203.18)
PB8: MCU (U100.45), Power (J203.22)
PB9: MCU (U100.46), Power (J203.21)
PB15: MCU (U100.28), Power (J203.14)
PB_DOWN: MCU (U100.25), INPUTS_OUTPUTS (C402.2 R422.2)
PB_MODE: MCU (U100.26), INPUTS_OUTPUTS (C401.2 R421.2)
PB_UP: MCU (U100.27), INPUTS_OUTPUTS (C400.2 R420.2)
PC13: MCU (U100.2), Power (J203.10)
PC14: MCU (U100.3), Power (J203.09)
PC15: MCU (U100.4), Power (J203.08)
PF0: MCU (U100.5), Power (J203.07)
PF1: MCU (U100.6), Power (J203.06)
PF6: MCU (U100.35), Power (J203.19)
PF7: MCU (U100.36), Power (J203.20)
R_SPEED_LED: MCU (U100.17), INPUTS_OUTPUTS (R403.1 R406.2)
R_TEMP_LED: MCU (U100.20), INPUTS_OUTPUTS (R414.1 R417.2)
SETTING_LED: MCU (U100.29), Power (J203.15), INPUTS_OUTPUTS (R428.1 R429.2)
SPEED_SENSOR_ANALOG_PIN: MCU (U100.13), INPUTS_OUTPUTS (J401.4)
SPEED_SENSOR_DIGITAL_PIN: MCU (U100.14), INPUTS_OUTPUTS (J401.3)
TEMPERATURE_SENSOR: MCU (U100.12), INPUTS_OUTPUTS (J402.2 R426.2)
USB_D_N: Communication (U301.3), Power (J200.2)
USB_D_P: Communication (U301.1), Power (J200.3)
